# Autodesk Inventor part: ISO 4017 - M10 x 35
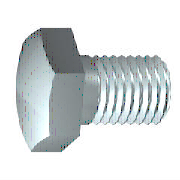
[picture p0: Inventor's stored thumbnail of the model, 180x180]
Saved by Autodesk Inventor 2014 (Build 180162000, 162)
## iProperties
Created: 2013-02
Part Number: ISO 4017 - M10 x 35
Material: Stainless Steel, 440C
Description: Hexagon head screws
Document SubType Name: Modeling
Standard: ISO 4017
Designer: Thom Tremblay
Standard Revision: Third edition 1999-08-15
Standards Organization: ISO
Language: en-US
Size Designation: M10 x 35
Categories: <MemberInstance><Categories><Category DisplayName="Fasteners" InternalName="e4da775c-781d-43d5-af7c-5136215cf5a6" Mnemonic="FSTN"><Category DisplayName="Bolts"
Density: 7.75 g/cm^3
Appearance: Semi-Polished
IsCustomPart: 0
Author: Thom Tremblay
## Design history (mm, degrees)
sketch "Sketch1"
  geometry: L1 (0, 7.315)-(0, 5); L2 (4.5, 5)-(35, 5); L3 (35, 5)-(35, 0); L4 (35, 0)-(-0.6, 0); L5 (-7.72, 0)-(42.12, 0) reference; L6 (-0.6, 0)-(-0.6, 7.315); L7 (-0.6, 7.315)-(0, 7.315); L8 (4.5, 5)-(3.58, 5); L9 (3.58, 5)-(0, 5); L10 (0, -1.463)-(0, 8.778) reference
  constraints: 16 end point, 2 collinear, 2 perpendicular, 1 parallel
  dimensions: "d0" = 35 distance between parallel lines of L3 L1 (= NLG); "d1" = 30.5 distance from line of L2.start L3 (= GEL); "d2" = 10 diameter of L2 L4 (= GD); "d9" = 0.6001 distance between parallel lines of L6 L1 (computed from SD); "d10" = 14.63 diameter of L7 L4 (= SD2); "d13" = 0.92028 distance of L2.start L8.end (computed from GAL); "d14" = 10 diameter of L9 L4 (= BDM)
revolve "Body" sketch "Sketch1" stored, may be unused: angle "d12" = 90 deg
sketch "Sketch2"
  geometry: L1 (0, 9.238)-(8, 4.619); L2 (8, 4.619)-(8, -4.619); L3 (8, -4.619)-(0, -9.238); L4 (0, -9.238)-(-8, -4.619); L5 (-8, -4.619)-(-8, 4.619); L6 (-8, 4.619)-(0, 9.238); 2 further points
  constraints: 12 end point, 1 coincident, 1 vertical, 11 other
  dimensions: "d11" = 16 distance between parallel lines of L5 L2 (= SW)
extrude "Head" join sketch "Sketch2" distance "d3" = 5.8 (= KOH - SD); taper "d4" = 0 deg
sketch "Sketch4"
  geometry: L1 (-6.4, 8)-(-6.4, 9.238); L2 (-6.4, 9.238)-(-5.686, 9.238); L3 (-5.686, 9.238)-(-6.4, 8); L4 (-7.56, 0)-(0.56, 0) reference; L5 (-0.6, 9.238)-(-6.4, 9.238) reference; L6 (-6.4, 4.619)-(-6.4, 9.238) reference
  constraints: 6 end point, 2 collinear, 1 perpendicular, 1 vertical
  dimensions: "d5" = 30 deg angle of L3 L1 (= ANG1); "d19" = 16 diameter of L1.start L4 (= SW0)
revolve "Chamfer1" sketch "Sketch4" stored, may be unused: angle "d21" = 90 deg
workplane "Work Plane1"
body "Solid1"
feature "Thread" dims "d15" = 30.5 (= GEL), "d16" = 0
chamfer "Chamfer2" distance "d6" = 0.92018 (= -0.5 x SPD + 0.5 x GD); stored, may be unused: second distance "d7" = 0.92028 (computed from GUL), angle "d55" = 45 deg
other parameters: "NLG" = 35 [user parameter; used in 1 equation term], "GD" = 10 (= NND) [user parameter; used in 2 equation terms], "BDM" = 10 (= NND) [user parameter; used in 1 equation term], "KOH" = 6.4 [user parameter; used in 1 equation term], "GEL" = 30.5 [user parameter; used in 2 equation terms], "SW" = 16 [user parameter; used in 2 equation terms], "SW0" = 16 (= SW) [user parameter; used in 1 equation term], "SPD" = 8.15965 (= NND - 1.2269 x PTC) [user parameter; used in 1 equation term], "SD2" = 14.63 [user parameter; used in 2 equation terms], "SD" = 0.6 [user parameter; used in 2 equation terms], "ANG1" = 30 deg [user parameter; used in 1 equation term], "GAL" = 0.92018 (= 0.61345 x PTC) [user parameter; used in 1 equation term], "GUL" = 0.92018 (= 0.61345 x PTC) [user parameter; used in 1 equation term], "d8" = 0, "RR" = 0.4 [user parameter], "d57" = 0, "d58" = 0, "TPU" = 6.66667 (computed from PTC) [user parameter], "GD1" = 8.15965 (= THREADDIA - 1.2269 x PTC) [user parameter], "SDH" = 14.63 (= SD2) [user parameter], "SDHG" = 4.5 [user parameter], "TOA" = 30 deg [user parameter], "PTC" = 1.5 [user parameter; used in 5 equation terms], "E0" = 18.48 [user parameter]
